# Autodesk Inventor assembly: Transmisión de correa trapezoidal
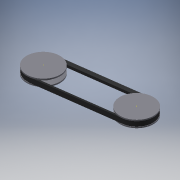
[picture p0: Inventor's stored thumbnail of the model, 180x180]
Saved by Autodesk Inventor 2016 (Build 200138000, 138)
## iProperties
ClientObjectVersion: 1
Created: 2016-06
Part Number: Transmisión de correa trapezoidal
Document SubType Name: Assembly
Designer: adm
Author: adm
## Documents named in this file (4)
- C:\Users\adm\Desktop\Alvarez\ensamblaje\Design Accelerator\Transmisión de correa trapezoidal1.iam
- C:\Users\adm\Desktop\Alvarez\ensamblaje\Design Accelerator\Correa trapezoidal1.ipt
- C:\Users\adm\Desktop\Alvarez\ensamblaje\Design Accelerator\Polea ranurada11.ipt
- C:\Users\adm\Desktop\Alvarez\ensamblaje\Design Accelerator\Polea ranurada21.ipt
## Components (3 placed, 3 different names)
1. Polea ranurada1:1 — Nivelación:1, Rotación:1
2. Polea ranurada2:1 — Nivelación:2, Rotación:1
3. Correa trapezoidal:1 — Nivelación:1, Nivelación:2
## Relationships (3: Flush 2, RelateRotation 1)
- Nivelación:1 [Flush]: Polea ranurada1:1 ↔ Correa trapezoidal:1
- Nivelación:2 [Flush]: Polea ranurada2:1 ↔ Correa trapezoidal:1
- Rotación:1 [RelateRotation]: Polea ranurada1:1 ↔ Polea ranurada2:1
